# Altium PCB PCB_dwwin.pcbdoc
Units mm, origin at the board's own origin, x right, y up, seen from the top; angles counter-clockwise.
Board outline 185.15 x 108 mm, 2 copper layers (Top Layer, Bottom Layer); 16 components, 14 nets, 161 pads, 6 vias.
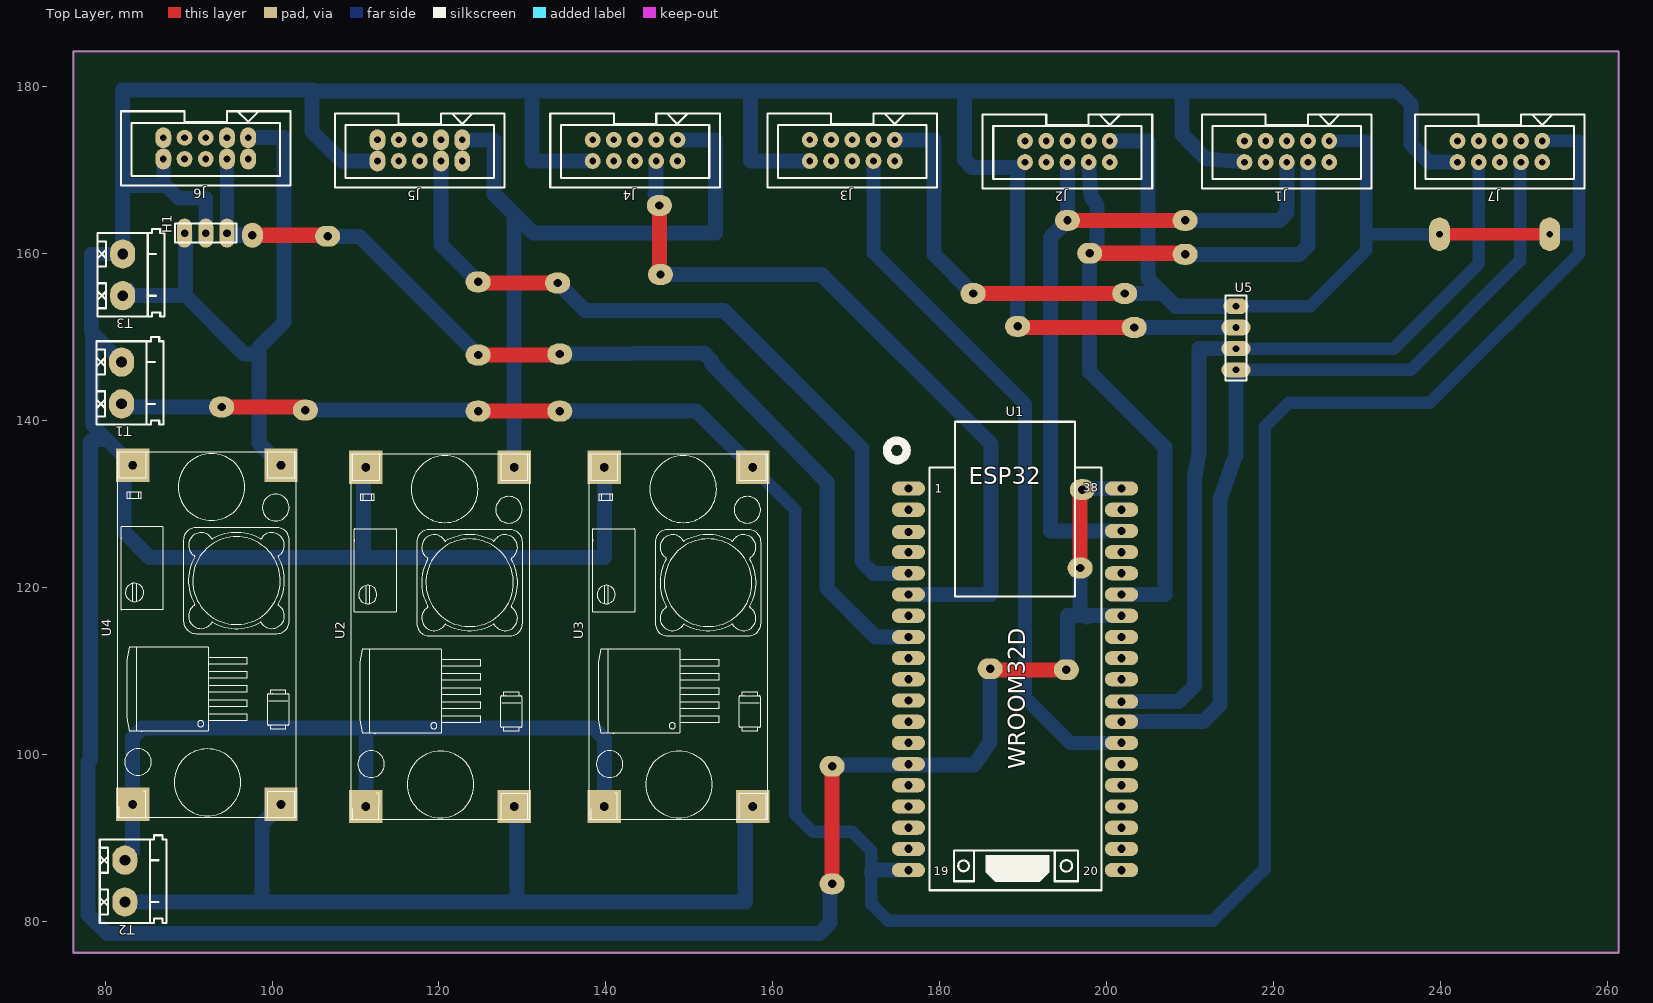
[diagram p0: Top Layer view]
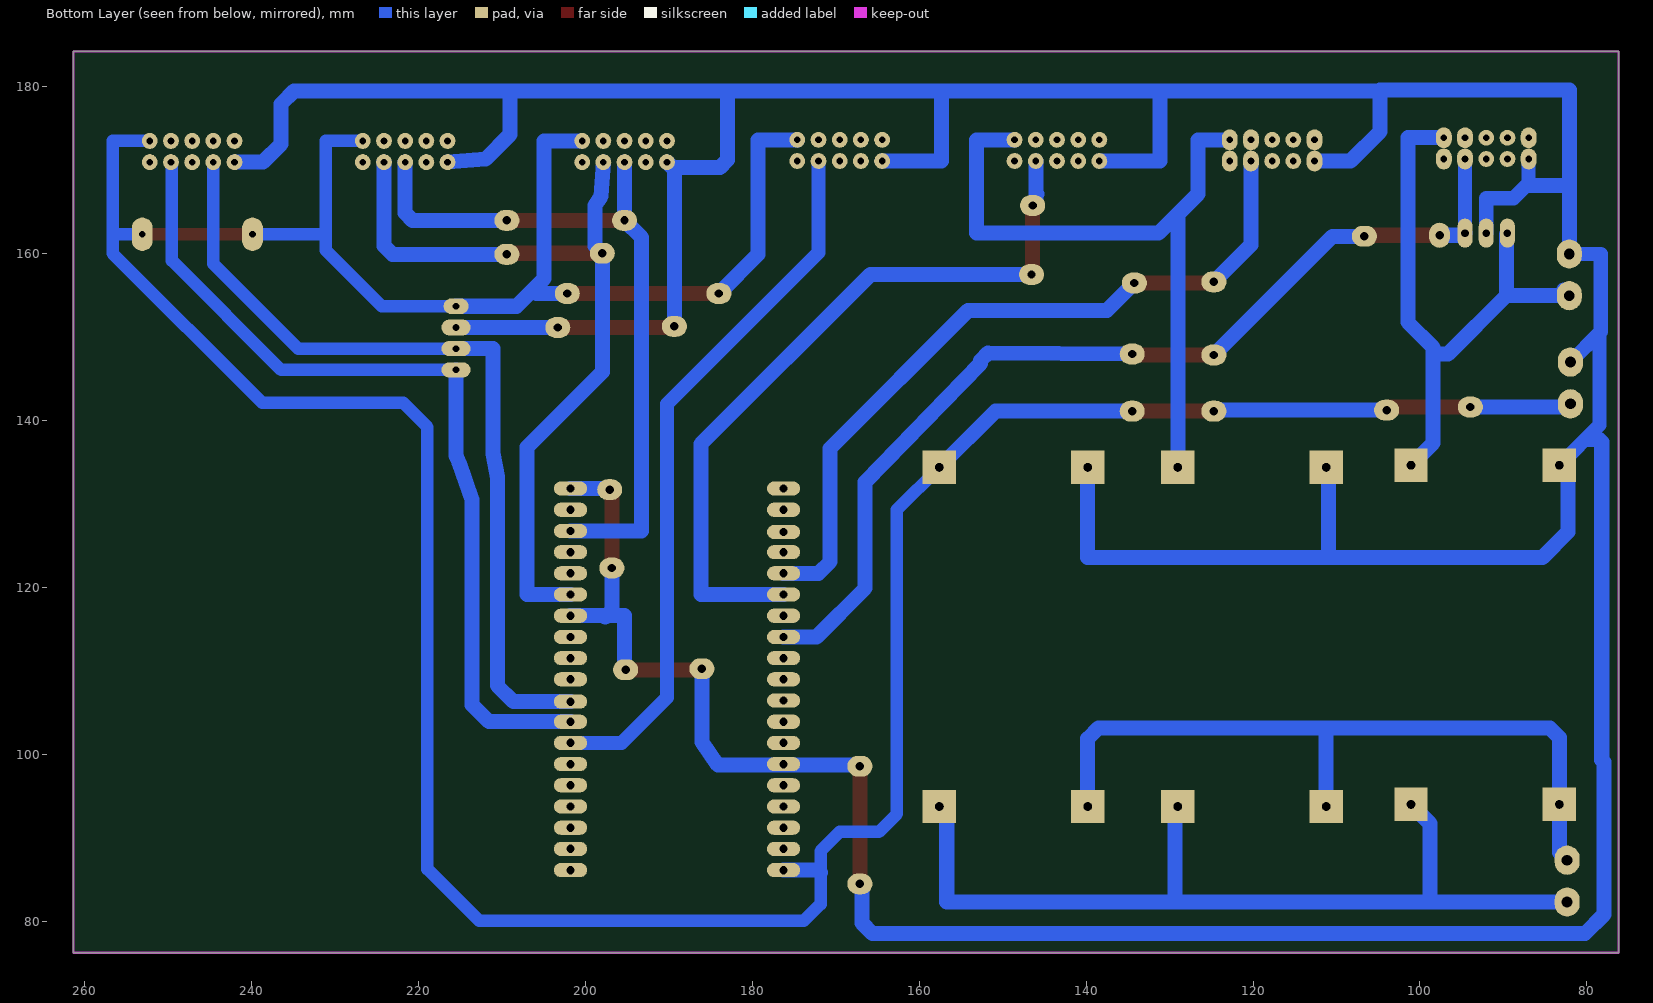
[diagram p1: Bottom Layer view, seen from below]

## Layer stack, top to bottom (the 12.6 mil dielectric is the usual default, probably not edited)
Top Layer: signal copper (thickness not stored)
Dielectric: dielectric 0.32, FR-4, Dk 4.8
Bottom Layer: signal copper (thickness not stored)

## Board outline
76.2,184.201 261.351,184.201 261.351,76.2 76.2,76.2

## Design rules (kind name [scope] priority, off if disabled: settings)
BoardOutlineClearance Default [All] p0: genericclearance=0.254 ignorepadtopadclearanceinfootprint=FALSE except(0: Region-CutoutEdge Arc-SplitContinuation Track-SplitContinuation SMDPad-SplitContinuation THPad-SplitContinuation Via-SplitContinuation Fill-SplitContinuation Poly-SplitContinuation Region-SplitContinuation Text-SplitContinuation; 0.599: Track-OutlineEdge SMDPad-OutlineEdge THPad-OutlineEdge Via-OutlineEdge Fill-OutlineEdge Region-OutlineEdge Poly-OutlineEdge Text-OutlineEdge Sheet-OutlineEdge Hole-OutlineEdge Track-CutoutEdge SMDPad-CutoutEdge THPad-CutoutEdge Via-CutoutEdge Fill-CutoutEdge Poly-CutoutEdge Text-CutoutEdge Sheet-CutoutEdge Hole-CutoutEdge)
Clearance Default [All] p1: gap=0.178 ignorepadtopadclearanceinfootprint=FALSE except(0: Region-Region; 0.599: Track-Track SMDPad-Track THPad-Track Via-Track Fill-Track Region-Track Poly-Track Text-Track Sheet-Track Hole-Track Track-SMDPad SMDPad-SMDPad THPad-SMDPad Via-SMDPad Fill-SMDPad Region-SMDPad Poly-SMDPad Text-SMDPad Sheet-SMDPad Hole-SMDPad Track-THPad SMDPad-THPad THPad-THPad Via-THPad Fill-THPad Region-THPad Poly-THPad Text-THPad Sheet-THPad Hole-THPad Track-Via SMDPad-Via THPad-Via Via-Via Fill-Via Region-Via Poly-Via Text-Via Sheet-Via Hole-Via Track-Fill SMDPad-Fill THPad-Fill Via-Fill Fill-Fill Region-Fill Poly-Fill Text-Fill Sheet-Fill Hole-Fill Track-Region SMDPad-Region THPad-Region Via-Region Fill-Region Poly-Region Text-Region Sheet-Region Hole-Region Track-Poly SMDPad-Poly THPad-Poly Via-Poly Fill-Poly Region-Poly Poly-Poly Text-Poly Sheet-Poly Hole-Poly Track-Text SMDPad-Text THPad-Text Via-Text Fill-Text Region-Text Poly-Text Text-Text Sheet-Text Hole-Text Track-Sheet SMDPad-Sheet THPad-Sheet Via-Sheet Fill-Sheet Region-Sheet Poly-Sheet Text-Sheet Sheet-Sheet Hole-Sheet Track-Hole SMDPad-Hole THPad-Hole Via-Hole Fill-Hole Region-Hole Poly-Hole Text-Hole Sheet-Hole Hole-Hole)
PasteMaskExpansion Common [All] p1: expansion=0
PlaneConnect Default [All] p1: planeconnectstyle=Relief reliefexpansion=0.508 reliefentries=4 reliefconductorwidth=0 reliefairgap=0.025
PolygonConnect Default [All] p1: connectstyle=Relief reliefentries=4 reliefconductorwidth=0 polygonreliefangle="90 Angle" airgapwidth=10
RoutingVias Default [All] p1: viastyle="Through Hole" holewidth=12.008000000000001 minholewidth=12.008000000000001 maxholewidth=2362 width=24.016000000000002 minwidth=24.016000000000002 maxwidth=3938
SolderMaskExpansion Common [All] p1: useseparateexpansions=TRUE expansion=2 expansionbottom=2
Width Default [All] p1: maxlimit=1000 minlimit=67 preferedwidth=67

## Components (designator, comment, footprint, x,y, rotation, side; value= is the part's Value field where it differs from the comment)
H1 "aux do" HEADER3X1 89.52,162.428 r90 top
J1 "bh1750" FRC10#1 219.06,172.207 r180 top
J2 "acd10(co2)" FRC10#1 192.771,172.207 r180 top
J3 "dht11" FRC10#1 166.99,172.334 r180 top
J4 "tds sensor" FRC10#1 140.955,172.334 r180 top
J5 "ph sensor" FRC10#2 115.174,172.334 r180 top
J6 "do sensor" FRC10#2 89.52,172.588 r180 top
J7 "lcd" FRC10#1 244.587,172.207 r180 top
T1 "5v" "M02 SCREW TERMINAL 5MM 10X8MM" 86.98,149.474 r180 top
T2 "main 12-24v dc" "M02 SCREW TERMINAL 5MM 10X8MM" 87.361,89.784 r180 top
T3 "9v" "M02 SCREW TERMINAL 5MM 10X8MM" 87.107,162.428 r180 top
U1 "WROOM32D-38 COPY" WROOM32D 176.261,131.821 r0 top
U2 "3.3v" LM2596:YAAJ_DCDC_STEPDOWN_LM2596 111.237,93.721 r90 top
U3 "5v" LM2596:YAAJ_DCDC_STEPDOWN_LM2596 139.812,93.721 r90 top
U4 "9v" LM2596:YAAJ_DCDC_STEPDOWN_LM2596 83.297,93.975 r90 top
U5 "aux lcd" HEADER4 215.504,149.855 r0 top

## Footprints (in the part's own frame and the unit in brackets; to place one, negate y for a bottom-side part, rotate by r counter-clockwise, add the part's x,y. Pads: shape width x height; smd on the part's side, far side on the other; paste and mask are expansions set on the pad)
FRC10#1 [mm]
  round 1.9 hole 0.8: 1(-7.62,-1.27) 2(-7.62,1.27) 3(-5.08,-1.27) 4(-5.08,1.27) 5(-2.54,-1.27) 6(-2.54,1.27) 7(0,-1.27) 8(0,1.27) 9(2.54,-1.27) 10(2.54,1.27)
  silkscreen extent -12.7,-4.45 7.62,4.45
FRC10#2 [mm]
  oval 1.9x2.5 hole 0.8: 1(-7.62,-1.27) 2(-7.62,1.27) 3(-5.08,-1.27) 4(-5.08,1.27) 9(2.54,-1.27) 10(2.54,1.27)
  round 1.9 hole 0.8: 5(-2.54,-1.27) 6(-2.54,1.27) 7(0,-1.27) 8(0,1.27)
  silkscreen extent -12.7,-4.45 7.62,4.45
HEADER3X1 [mm]
  oval 3.5x1.8 hole 0.914: 1(0,0) 2(0,-2.54) 3(0,-5.08)
  silkscreen extent -1.14,-6.22 1.14,1.14
HEADER4 [mm]
  oval 3x1.9 hole 0.8: 1(0,3.81)
  oval 3.5x1.9 hole 0.8: 2(0,1.27)
  oval 3.5x1.8 hole 0.8: 3(0,-1.27) 4(0,-3.81)
  silkscreen extent -1.27,-5.08 1.27,5.08
LM2596:YAAJ_DCDC_STEPDOWN_LM2596 [mm]
  rect 4x4 hole 1 slot 1.005 at 0 deg: 1(0,0) 2(0,-17.78) 3(40.64,-17.78) 4(40.64,0)
  silkscreen extent -1.55,-19.61 42.22,1.83
"M02 SCREW TERMINAL 5MM 10X8MM" [mm]
  oval 3x3.5 hole 1.3: 1(5,7.5) 2(5,2.5)
  silkscreen extent 0,-0.5 8,10
WROOM32D [mm]
  oval 4x1.7 hole 1: 1(0,0) 2(0,-2.54) 3(0,-5.207) 4(0,-7.62) 5(0,-10.16) 6(0,-12.7) 7(0,-15.24) 8(0,-17.78) 9(0,-20.32) 10(0,-27.94) 10(0,-22.86) 11(0,-25.4) 13(0,-30.48) 14(0,-33.02) 15(0,-35.56) 16(0,-38.1) 17(0,-40.64) 18(0,-43.18) 19(0,-45.72) 20(25.527,-45.72) 21(25.527,-43.18) 22(25.527,-40.64) 23(25.527,-38.1) 24(25.527,-35.56) 25(25.527,-33.02) 26(25.527,-30.48) 27(25.527,-27.94) 28(25.527,-25.527) 29(25.527,-22.86) 30(25.527,-20.32) 31(25.527,-17.78) 32(25.527,-15.24) 33(25.527,-12.7) 34(25.527,-10.16) 35(25.527,-7.62) 36(25.527,-5.08) 37(25.527,-2.54) 38(25.527,0)
  silkscreen extent -2.56,-48.13 23.11,8

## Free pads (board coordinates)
  oval 3x2.5 hole 1: 1(146.543,157.475) 2(146.416,165.73) 3(124.699,156.586) 5(134.224,156.459) 9(134.478,147.95) 10(124.699,147.823) 11(106.665,162.047) 13(134.478,141.092) 14(124.699,141.092) 15(103.998,141.219) 16(93.965,141.6) 17(186.04,110.231) 18(195.184,110.104) 19(197.978,160.015) 20(209.408,159.888) 21(209.408,163.952) 22(195.311,163.952) 23(196.835,122.296) 24(197.089,131.694) 25(167.117,84.45) 26(167.117,98.547) 28(203.312,151.125) 29(189.342,151.252) 31(202.169,155.189) 33(184.008,155.189)
  oval 2.5x3 hole 1: 12(97.648,162.174)
  oval 2.5x4 hole 0.8: 34(253.096,162.301) 35(239.888,162.301)

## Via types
v1: diameter 0.62, hole 0.31, Top Layer to Bottom Layer, 6 vias

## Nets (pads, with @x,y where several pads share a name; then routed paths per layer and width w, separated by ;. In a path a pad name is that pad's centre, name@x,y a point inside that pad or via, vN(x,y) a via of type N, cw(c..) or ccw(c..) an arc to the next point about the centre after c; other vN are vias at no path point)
3.3: J4.1 J5.1 U2.3 | length 88.5
  Bottom Layer w1.8: J5.1 126.604,173.604 126.604,167.127 ; U2.3@129.017,134.107 129.017,164.714 126.604,167.127 ; J4.1 153.147,173.604 153.147,162.428 131.303,162.428 126.604,167.127
9: H1.1 J6.1 T3.1 U4.3 | length 73.7
  Bottom Layer w1.7: T3.1 82.107,155.015 T3.1@82.766,155.674
  Bottom Layer w1.8: T3.1 89.654,154.928 ; H1.1 89.654,162.294 89.654,154.928 ; J6.1 101.458,173.858 101.458,151.76 98.41,148.712 98.41,137.282 U4.3 ; 98.41,147.95 96.632,147.95 89.654,154.928
+5V: J1.1 J2.1 J3.1 J7.1 pad.13 pad.14 pad.15 pad.16 pad.31 pad.33 pad.34 pad.35 T1.1 U1.19 U3.3 U5.1 | length 458.5
  Top Layer w1.5: pad.35 pad.34
  Top Layer w1.8: pad.16 103.617,141.6 v1(103.998,141.219) ; pad.14 pad.13 ; pad.33 pad.31
  Bottom Layer w0.5: 171.816,86.101 U1.19
  Bottom Layer w1.5: U3.3 162.672,129.281 162.672,92.832 164.831,90.673 169.53,90.673 171.816,88.387 171.816,85.813 171.816,82.037 173.848,80.005 212.71,80.005 218.933,86.228 218.933,139.187 221.854,142.108 238.745,142.108 256.652,160.015 256.652,162.301 ; U5.1 224.394,153.665 231.125,160.396 231.125,173.477 J1.1 ; 231.125,162.301 pad.35 ; J7.1 256.652,173.477 256.652,162.301 ; pad.34 256.652,162.301
  Bottom Layer w1.8: T1.1 82.354,141.6 pad.16 ; v1(103.998,141.219) 124.572,141.219 pad.14 ; pad.13 150.861,141.092 U3.3 ; 171.816,85.813 172.103,86.101 U1.19 ; J3.1 179.309,173.604 179.309,159.888 pad.33 ; J2.1 204.963,173.477 204.963,156.967 208.265,153.665 U5.1 ; pad.31 205.844,155.189 206.293,155.637
A/O1: J4.4 pad.1 pad.2 U1.6 | length 91.4
  Top Layer w1.8: pad.2 146.416,157.602 pad.1
  Bottom Layer w1.8: 145.908,167.127 146.289,165.73 pad.2 146.035,166.111 J4.4 ; pad.1 165.847,157.475 186.167,137.155 186.167,119.121 U1.6
A/O2: J5.4 pad.3 pad.5 U1.5 | length 90.3
  Top Layer w1.8: pad.3 124.826,156.459 pad.5
  Bottom Layer w1.8: J5.4 120.254,161.031 pad.3 ; pad.5 137.526,153.157 154.163,153.157 170.673,136.647 170.673,123.058 172.07,121.661 U1.5
DATA1: J3.4 U1.26 | length 85.6
  Bottom Layer w1.7: J3.4 172.07,160.124 190.231,141.963 190.231,106.802 195.692,101.341 U1.26
DO: H1.3 J6.4 pad.9 pad.10 pad.11 pad.12 U1.8 | length 118.5
  Top Layer w1.8: pad.12 106.538,162.174 v1(106.665,162.047) ; pad.10 134.351,147.823 pad.9
  Bottom Layer w1.7: H1.3 J6.4
  Bottom Layer w1.8: H1.3 94.854,162.174 pad.12 ; v1(106.665,162.047) 110.475,162.047 pad.10 ; pad.9 151.75,148.077 152.639,147.188 152.639,146.807 166.482,132.583 166.482,119.883 172.324,114.041 U1.8
GND: H1.2 J1.10 J2.10 J3.10 J4.10 J5.10 J6.10 J7.10 pad.17 pad.18 pad.23 pad.24 pad.25 pad.26 pad.28 pad.29 T1.2 T3.2 U1.14 U1.32 U1.38 U2.4 U3.4 U4.4 U5.2 | length 694.2
  Top Layer w1.8: pad.25 v1(167.117,98.547) ; v1(186.04,110.231) 186.167,110.104 pad.18 ; pad.29 189.469,151.125 pad.28 ; pad.23 196.835,131.694 pad.24
  Bottom Layer w1.7: T3.2 78.344,159.929 78.344,150.609 81.978,146.975 78.471,150.482 78.471,139.441 U4.4 ; J6.10 86.98,168.408 88.783,166.604 92.06,166.604 H1.2
  Bottom Layer w1.8: 79.708,137.696 78.503,137.696 78.217,137.409 78.217,99.309 77.963,99.055 77.963,80.767 80.249,78.481 165.593,78.481 166.863,79.751 166.863,84.196 pad.25 ; 82.105,168.143 82.105,179.573 104.76,179.573 104.76,174.62 108.316,171.064 J5.10 ; T3.2 82.107,168.143 86.98,168.143 ; U4.4 82.281,133.599 82.281,126.614 85.329,123.566 110.983,123.566 ; 104.76,179.446 209.027,179.446 ; U2.4@111.237,134.107 110.983,133.853 110.983,123.566 ; 131.176,179.446 131.176,171.064 J4.10 ; U3.4 139.812,123.566 110.983,123.566 ; 157.338,179.446 157.338,171.064 J3.10 ; v1(167.117,98.547) 167.117,98.674 178.928,98.674 184.135,98.674 186.04,101.468 186.04,102.103 v1(186.04,110.231) ; 182.966,179.446 182.966,171.217 183.881,170.302 189.596,170.302 J2.10 189.342,170.048 pad.29 ; pad.18@195.311,110.739 195.311,116.581 U1.32 ; pad.23 196.835,117.243 197.624,116.454 ; pad.24 197.216,131.821 U1.38 ; pad.28 U5.2 ; J1.10 211.948,171.318 209.027,174.239 209.027,179.446 ; J7.10 238.618,170.937 236.459,173.096 236.459,177.922 234.935,179.446 209.027,179.446
RX: J7.4 U1.27 U5.4 | length 104.4
  Bottom Layer w1.5: U5.4 236.459,146.045 249.54,159.126 249.54,170.81 J7.4
  Bottom Layer w1.8: U1.27 211.567,103.881 213.599,105.913 213.599,130.487 215.123,134.869 215.504,135.758 U5.4
SCL1: J1.6 J2.6 pad.21 pad.22 U1.36 | length 86.6
  Top Layer w1.8: pad.22@195.311,163.825 pad.22 pad.21
  Bottom Layer w1.8: J2.6 pad.22 193.279,161.92 193.279,126.741 U1.36 ; v1(209.408,164.079) pad.21 220.711,163.952 221.6,164.841 J1.6
SDA1: J1.4 J2.4 pad.19 pad.20 U1.33 | length 98
  Top Layer w1.8: pad.19 209.281,160.015 v1(209.408,159.888)
  Bottom Layer w1.8: J2.4 198.105,166.873 198.867,165.73 198.867,160.904 pad.19 197.978,145.791 206.995,136.774 206.995,119.121 U1.33 ; v1(209.408,159.888) 223.124,159.888 224.14,160.904 J1.4
TX: J7.8 U1.28 U5.3 | length 99.9
  Bottom Layer w1.5: U5.3 234.427,148.585 244.587,158.745 J7.8
  Bottom Layer w1.8: U1.28 208.646,106.294 210.551,108.199 210.551,133.177 211.059,136.012 211.059,148.585 U5.3
U2_1: T2.2 U2.1 U3.1 U4.1 | length 91.6
  Bottom Layer w1.7: U4.1@82.877,94.864 83.297,94.444 U4.1
  Bottom Layer w1.8: T2.2@82.361,87.284 83.297,88.22 U4.1 83.297,101.976 84.44,103.119 111.745,103.119 ; U2.1@111.237,93.467 111.237,102.611 111.745,103.119 ; U3.1 139.812,101.849 138.542,103.119 111.745,103.119
U2_2: T2.1 U2.2 U3.2 U4.2 | length 110.1
  Bottom Layer w1.8: T2.1@82.361,82.284 98.791,82.284 ; U4.2 98.791,91.689 98.791,82.284 ; U2.2@129.017,93.467 129.353,93.131 129.353,82.284 ; U3.2 156.703,92.832 156.703,82.284 98.791,82.284
pads on no net: J1.2 J1.3 J1.5 J1.7 J1.8 J1.9 J2.2 J2.3 J2.5 J2.7 J2.8 J2.9 J3.2 J3.3 J3.5 J3.6 J3.7 J3.8 J3.9 J4.2 J4.3 J4.5 J4.6 J4.7 J4.8 J4.9 J5.2 J5.3 J5.5 J5.6 J5.7 J5.8 J5.9 J6.2 J6.3 J6.5 J6.6 J6.7 J6.8 J6.9 J7.2 J7.3 J7.5 J7.6 J7.7 J7.9 U1.1 U1.2 U1.3 U1.4 U1.7 U1.9 U1.10 U1.11 U1.13 U1.15 U1.16 U1.17 U1.18 U1.20 U1.21 U1.22 U1.23 U1.24 U1.25 U1.29 U1.30 U1.31 U1.34 U1.35 U1.37

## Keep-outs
Board Outline Layer:
  the board outline again, w0.254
